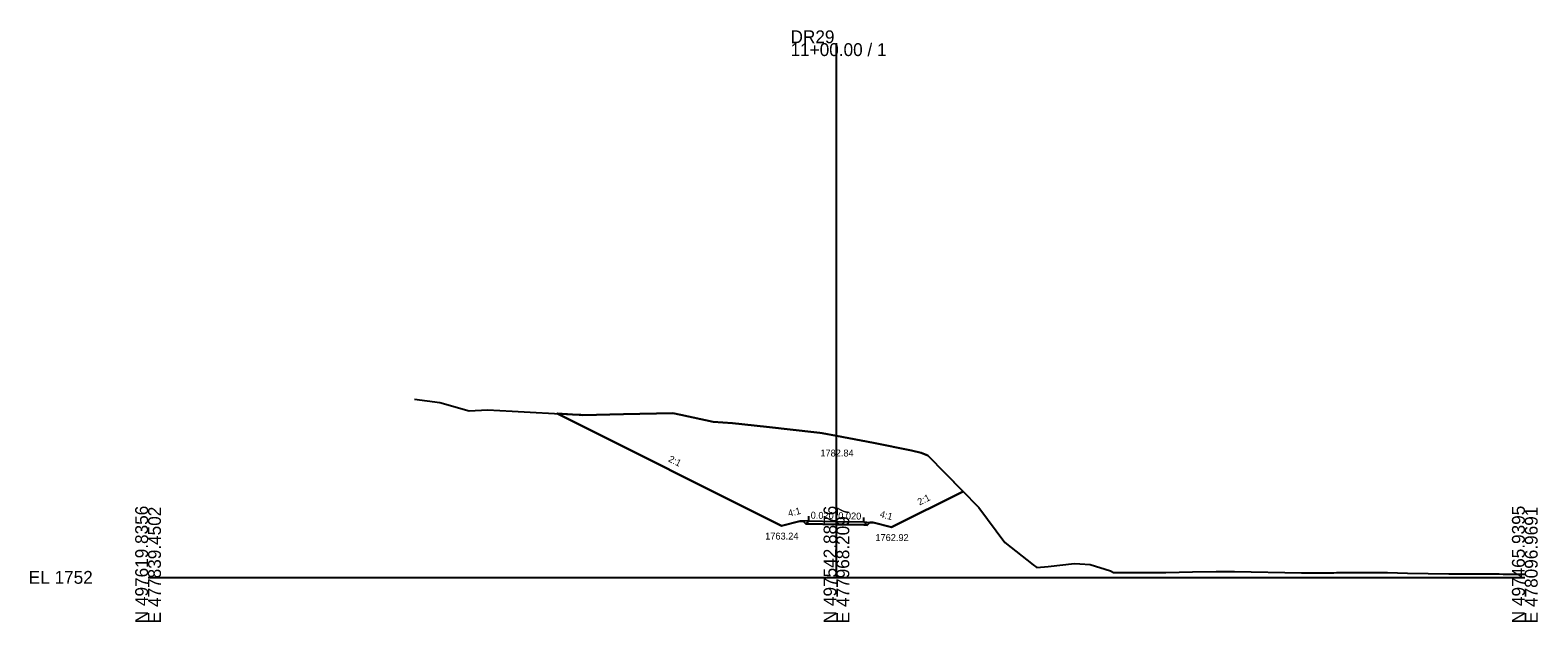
# Model space of a CAD drawing. Extents: x -26 to 303, y -10 to 4734.
# Drawn here: x -25.7 to 302.8, y 1990.3 to 2119.2 of the extents above; entities that cross this region are included whole.
import ezdxf

# ---------------------------------------------------------------- set-up
doc = ezdxf.new("R2010")
doc.units = 0
for name, color, linetype in [('Exist Cross Section Cell', 7, 'Continuous'), ('Exist XS Center Line Elevation Label', 7, 'Continuous'), ('Exist XS Ground Line', 7, 'Continuous'), ('Prop XS Ditch Slope Text', 7, 'Continuous'), ('Prop XS Ditch Standard Text', 7, 'Continuous'), ('Prop XS Dump Level', 7, 'Continuous'), ('Prop XS Earthwork Shape', 7, 'Continuous'), ('Prop XS EOT Tick Mark', 7, 'Continuous'), ('Prop XS Finish Grade', 7, 'Continuous'), ('Prop XS Finish Grade Earthwork', 7, 'Continuous'), ('Prop XS Finish Grade Pavement', 7, 'Continuous'), ('Prop XS Pvmt Edge Slope', 7, 'Continuous'), ('Prop XS SE Text', 7, 'Continuous'), ('Prop XS Shoulder Borrow Shape', 7, 'Continuous'), ('Prop XS Side Slope Text', 7, 'Continuous'), ('Prop XS Subgrade Earthwork', 7, 'Continuous')]:
    doc.layers.add(name, color=color, linetype=linetype)

msp = doc.modelspace()

# ---------------------------------------------------------------- linework, layer by layer
at = {"layer": 'Exist Cross Section Cell'}
for p, q in [((150, 2000), (150, 2116.39)), ((0, 2000), (150, 2000)), ((150, 2000), (300, 2000))]:
    msp.add_line(p, q, dxfattribs=at)
at = {"layer": 'Exist XS Ground Line'}
msp.add_lwpolyline([(58.03, 2038.8), (63.59, 2038.09), (69.97, 2036.32), (73.93, 2036.48), (79.32, 2036.23), (92.48, 2035.49), (93.91, 2035.4), (94.3, 2035.38), (94.73, 2035.37), (103.6, 2035.55), (114.35, 2035.76), (116.12, 2035.41), (123.11, 2033.89), (127.36, 2033.59), (134.76, 2032.79), (145.74, 2031.56), (146.41, 2031.49), (146.86, 2031.42), (150, 2030.84), (158.06, 2029.34), (166.36, 2027.65), (168.46, 2027.1), (169.92, 2026.56), (181.01, 2015.21), (186.68, 2007.61), (192.85, 2002.7), (193.69, 2002.14), (196.16, 2002.36), (201.88, 2003), (203.07, 2002.92), (205.3, 2002.79), (209.74, 2001.45), (210.39, 2001.06), (220.81, 2001.04), (221.2, 2001.03), (221.77, 2001.04), (227.58, 2001.17), (232.75, 2001.27), (236.77, 2001.26), (251.32, 2000.99), (256.56, 2000.98), (257.01, 2000.99), (258.35, 2001.02), (258.94, 2001.03), (259.68, 2001.03), (260.84, 2001.04), (262.33, 2001.05), (263.34, 2001.06), (267.97, 2001.04), (269.45, 2001.05), (270.1, 2001.05), (274.42, 2000.93), (283.41, 2000.8), (285.66, 2000.78), (286.02, 2000.77), (286.6, 2000.77), (287.59, 2000.77), (290.13, 2000.76), (294.38, 2000.74), (295.26, 2000.73), (296.57, 2000.72), (297.39, 2000.71), (298.53, 2000.69), (300, 2000.67)], dxfattribs=at)
at = {"layer": 'Prop XS Dump Level'}
for p, q in [((144, 2012.32), (150, 2012.2)), ((150, 2012.2), (156, 2012.08))]:
    msp.add_line(p, q, dxfattribs=at)
at = {"layer": 'Prop XS Earthwork Shape'}
for points in [[(127.36, 2033.59), (134.76, 2032.79), (145.74, 2031.56), (146.41, 2031.49), (146.86, 2031.42), (150, 2030.84), (158.06, 2029.34), (166.36, 2027.65), (168.46, 2027.1), (169.92, 2026.56), (177.58, 2018.71), (162, 2010.92), (158, 2011.92), (157.26, 2011.98), (156.68, 2011.4), (156, 2011.41), (150, 2011.53), (144, 2011.65), (143.35, 2011.67), (142.74, 2012.27), (142, 2012.24), (138, 2011.24), (89.13, 2035.67), (92.48, 2035.49), (93.91, 2035.4), (94.3, 2035.38), (94.73, 2035.37), (103.6, 2035.55), (114.35, 2035.76), (116.12, 2035.41), (123.11, 2033.89)], [(156, 2011.41), (156.68, 2011.4), (157.26, 2011.98), (158, 2011.92), (162, 2010.92), (177.58, 2018.71), (169.92, 2026.56), (168.46, 2027.1), (166.36, 2027.65), (158.06, 2029.34), (150, 2030.84), (146.86, 2031.42), (146.41, 2031.49), (145.74, 2031.56), (134.76, 2032.79), (127.36, 2033.59), (123.11, 2033.89), (116.12, 2035.41), (114.35, 2035.76), (103.6, 2035.55), (94.73, 2035.37), (94.3, 2035.38), (93.91, 2035.4), (92.48, 2035.49), (89.13, 2035.67), (138, 2011.24), (142, 2012.24), (142.74, 2012.27), (143.35, 2011.67), (144, 2011.65), (150, 2011.53)]]:
    msp.add_lwpolyline(points, close=True, dxfattribs=at)
at = {"layer": 'Prop XS EOT Tick Mark'}
for p, q in [((144, 2012.32), (144, 2013.32)), ((156, 2012.08), (156, 2013.08))]:
    msp.add_line(p, q, dxfattribs=at)
at = {"layer": 'Prop XS Finish Grade'}
for p, q in [((144, 2012.32), (142.74, 2012.27)), ((156, 2012.08), (157.26, 2011.98))]:
    msp.add_line(p, q, dxfattribs=at)
at = {"layer": 'Prop XS Finish Grade Earthwork'}
for p, q in [((138, 2011.24), (89.13, 2035.67)), ((162, 2010.92), (177.58, 2018.71)), ((142, 2012.24), (138, 2011.24)), ((142.74, 2012.27), (142, 2012.24)), ((157.26, 2011.98), (158, 2011.92)), ((158, 2011.92), (162, 2010.92))]:
    msp.add_line(p, q, dxfattribs=at)
at = {"layer": 'Prop XS Finish Grade Pavement'}
for p, q in [((144, 2012.32), (150, 2012.2)), ((150, 2012.2), (156, 2012.08))]:
    msp.add_line(p, q, dxfattribs=at)
at = {"layer": 'Prop XS Pvmt Edge Slope'}
for p, q in [((144, 2012.32), (143.35, 2011.67)), ((156, 2012.08), (156.68, 2011.4))]:
    msp.add_line(p, q, dxfattribs=at)
at = {"layer": 'Prop XS Shoulder Borrow Shape'}
for points in [[(144, 2012.32), (142.74, 2012.27), (143.35, 2011.67)], [(156, 2012.08), (157.26, 2011.98), (156.68, 2011.4)]]:
    msp.add_lwpolyline(points, close=True, dxfattribs=at)
at = {"layer": 'Prop XS Subgrade Earthwork'}
for p, q in [((143.35, 2011.67), (142.74, 2012.27)), ((144, 2011.65), (143.35, 2011.67)), ((150, 2011.53), (144, 2011.65)), ((156, 2011.41), (150, 2011.53)), ((156, 2011.41), (156.68, 2011.4)), ((156.68, 2011.4), (157.26, 2011.98))]:
    msp.add_line(p, q, dxfattribs=at)

# ---------------------------------------------------------------- texts
at = {"layer": 'Exist Cross Section Cell'}
for s, p in [('DR29', (140, 2116.39)), ('11+00.00 / 1', (140, 2113.59)), ('EL 1752', (-26, 1998.6))]:
    msp.add_text(s, height=2.8, dxfattribs=at).set_placement(p)
for s, p in [('N 497619.8356', (0, 1990)), ('E 477839.4502', (2.8, 1990)), ('N 497542.8876', (150, 1990)), ('E 477968.2097', (152.8, 1990)), ('N 497465.9395', (300, 1990)), ('E 478096.9691', (302.8, 1990))]:
    msp.add_text(s, height=2.8, rotation=90, dxfattribs=at).set_placement(p)
at = {"layer": 'Exist XS Center Line Elevation Label'}
msp.add_text('1782.84', height=1.5, dxfattribs=at).set_placement((146.5, 2026.34))
at = {"layer": 'Prop XS Ditch Slope Text'}
for rotation, p in [(14.0362, (139.64, 2013.19)), (345.9638, (159.33, 2013.13))]:
    msp.add_text('4:1', height=1.5, rotation=rotation, dxfattribs=at).set_placement(p)
at = {"layer": 'Prop XS Ditch Standard Text'}
for s, p in [('1763.24', (134.47, 2008.24)), ('1762.92', (158.49, 2007.92))]:
    msp.add_text(s, height=1.5, dxfattribs=at).set_placement(p)
at = {"layer": 'Prop XS Dump Level'}
for p in [(142, 2012.2), (158, 2011.88)]:
    msp.add_text('Case1', height=0.04, dxfattribs=at).set_placement(p)
at = {"layer": 'Prop XS SE Text'}
for p in [(144.38, 2012.81), (150.38, 2012.69)]:
    msp.add_text('0.020', height=1.5, rotation=358.8542, dxfattribs=at).set_placement(p)
at = {"layer": 'Prop XS Side Slope Text'}
for rotation, p in [(333.4349, (113.22, 2025.31)), (26.5651, (168.11, 2015.65))]:
    msp.add_text('2:1', height=1.5, rotation=rotation, dxfattribs=at).set_placement(p)

doc.saveas('drawing.dxf')
